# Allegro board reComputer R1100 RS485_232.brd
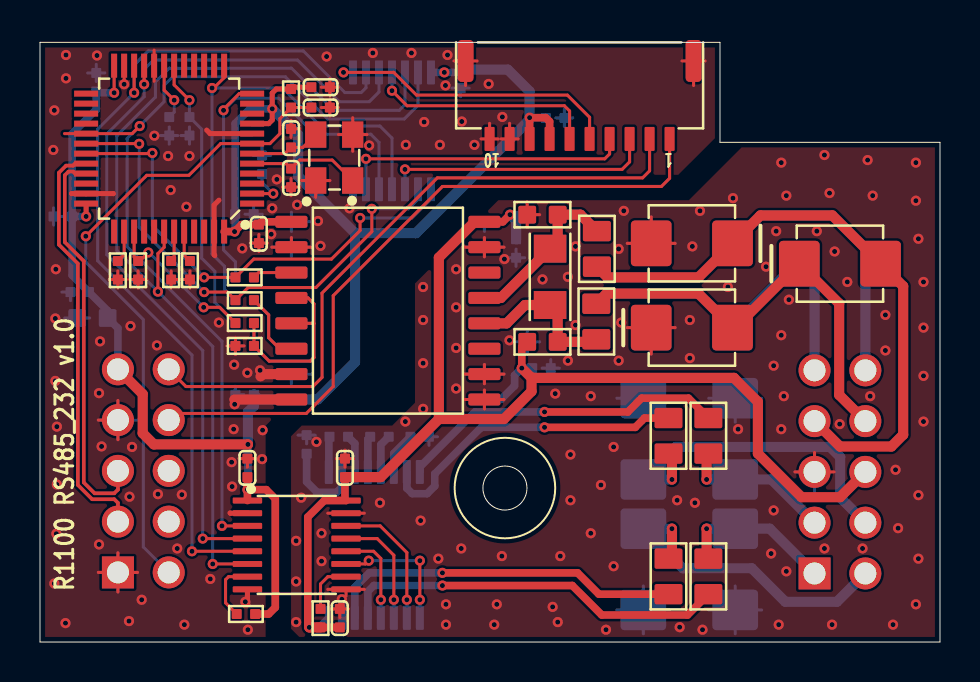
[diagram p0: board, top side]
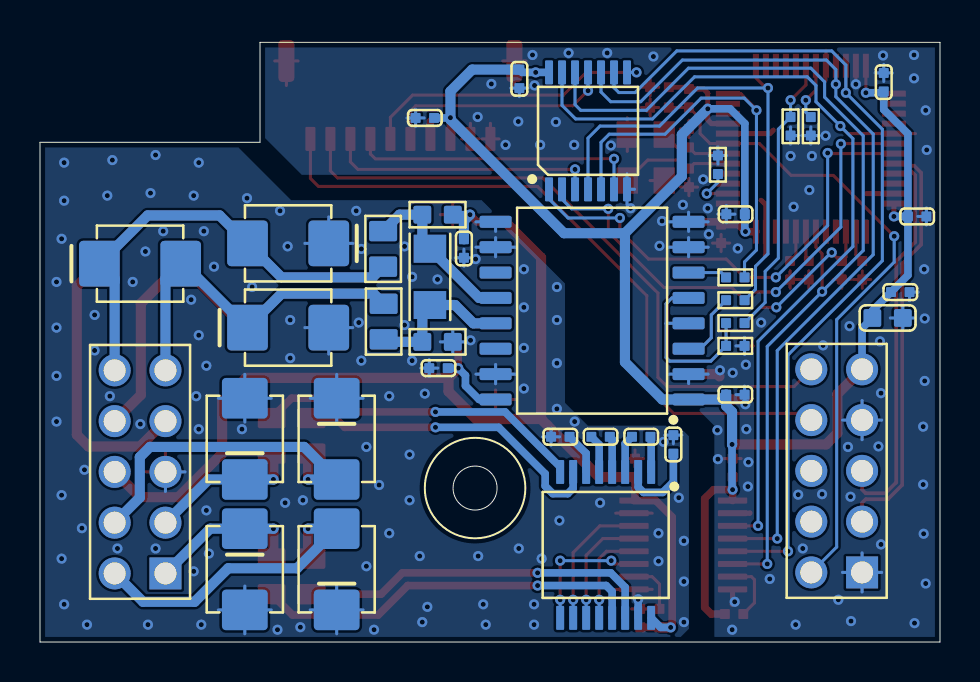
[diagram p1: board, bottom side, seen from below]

Outline 45 x 30 mm; copper layers: TOP, BOTTOM. Coordinates in mm from the lower left corner of the outline.
Outline path: circle c23.25,7.7 r1.1 ; 0,30 0,0 45,0 45,25 34,25 34,30 0,30

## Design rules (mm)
constraint set DEFAULT: min track width 0.152
net group DP1: nets USB_HUB1_DM2 USB_HUB1_DP2
net group N14652: nets N14652 N14700
net group N14712: nets N14712 N14756
net group RS485_2: nets EXT_RS485_1_B EXT_RS485_2_A
net group 5V_ISO_OUT: nets 5V_ISO_OUT RS485_1_A RS485_2_A
net group RS485_1: nets RS485_1_B

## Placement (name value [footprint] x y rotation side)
C1  100nF  [C0402]  10.94 20.42 270 top
C2  100nF  [C0402]  23.8 19.69 270 bottom
C3  100nF  [C0402]  10.22 21.4 0 bottom
C4  10uF  [C0603]  2.62 16.21 0 bottom
C5  1uF  [C0402]  14.03 27.76 180 top
C6  100nF  [C0402]  1.99 17.51 180 bottom
C7  100nF  [C0402]  10.23 12.38 180 bottom
C8  100nF  [C0402]  25.07 13.7 0 bottom
C9  100nF  [C0402]  14.03 26.74 0 top
C10  100nF  [C0402]  16.97 10.27 0 bottom
C11  100nF  [C0402]  14.94 10.27 0 bottom
C12  100nF  [C0402]  18.98 10.27 0 bottom
C13  100nF  [C0402]  13.33 9.89 90 bottom
C14  100nF  [C0402]  14.99 1.19 90 top
C15  100nF  [C0402]  2.81 28.01 90 bottom
C16  100nF  [C0402]  1.14 21.29 180 bottom
C17  100nF  [C0402]  15.25 8.71 90 top
C18  100nF  [C0402]  10.37 8.71 270 top
C19  100nF  [C0402]  21.03 28.17 270 bottom
C20  100nF  [C0402]  25.76 26.22 0 bottom
C21  22pF  [C0402]  12.55 23.22 270 top
C22  22pF  [C0402]  12.55 25.21 90 top
D1  SMBJ13CATR7  [DO_214AA_SMB]  32.59 15.73 180 top
D2  SMBJ13CATR7  [DO_214AA_SMB]  40 18.93 180 top
D3  SMBJ13CATR7  [DO_214AA_SMB]  32.59 19.95 0 top
D4  SMBJ13CATR7  [DO_214AA_SMB]  32.59 19.94 180 bottom
D5  SMBJ13CATR7  [DO_214AA_SMB]  40 18.93 0 bottom
D6  SMBJ13CATR7  [DO_214AA_SMB]  32.59 15.73 0 bottom
D7  SMBJ16CA  [DO_214AA_SMB]  30.17 3.64 270 bottom
D9  SMBJ16CA  [DO_214AA_SMB]  34.76 3.64 90 bottom
D10  SMBJ16CA  [DO_214AA_SMB]  30.17 10.16 90 bottom
D11  SMBJ16CA  [DO_214AA_SMB]  34.76 10.16 270 bottom
J1  Header 2x5 2.54  [HEADER2X5P_2D54_1_DIP]  5.17 8.56 0 bottom
J2  Header 2x5 2.54  [HEADER2X5P_2D54_1_DIP]  40 8.51 0 bottom
J3  1.0-10A-WT  [JST10_2P_1D0_12_35X4_3X3_2MM]  26.98 25.17 180 top
R1  10K  [R0603]  25.12 15.02 0 top
R2  33R  [R0402]  10.24 18.24 0 top
R3  RC0805FR-0710RL  [R0805]  27.82 16.03 90 top
R4  0R  [R0402]  10.24 15.96 0 top
R5  RC0805FR-0710RL  [R0805]  27.84 19.67 270 top
R6  33R  [R0402]  10.24 17.1 0 top
R7  10K  [R0402]  10.24 14.81 180 top
R8  120R  [R1206]  25.5 18.27 90 top
R9  10K  [R0402]  7.5 18.6 90 top
R10  10K  [R0603]  25.12 21.38 180 top
R11  10K  [R0402]  12.55 27.2 270 top
R12  10K  [R0603]  25.12 21.38 0 bottom
R13  33R  [R0402]  10.24 17.1 0 bottom
R14  RC0805FR-0710RL  [R0805]  27.84 19.67 270 bottom
R15  0R  [R0402]  10.24 15.96 0 bottom
R16  RC0805FR-0710RL  [R0805]  27.82 16.03 90 bottom
R17  33R  [R0402]  10.24 18.24 0 bottom
R18  10K  [R0402]  10.24 14.81 180 bottom
R19  120R  [R1206]  25.5 18.27 270 bottom
R20  10K  [R0603]  25.12 15.02 180 bottom
R25  10K  [R0402]  10.3 1.4 180 top
R26  10K  [R0402]  14.03 1.19 90 top
R27  10K  [R0402]  4.91 18.6 270 top
R28  10K  [R0402]  11.1 23.88 270 bottom
R29  10K  [R0402]  3.89 18.6 270 top
R30  10K  [R0402]  7.47 25.8 270 bottom
R31  10K  [R0402]  6.46 25.8 90 bottom
R32  10K  [R0402]  6.56 18.6 90 top
R33  100R  [R0805]  31.42 3.28 90 top
R34  100R  [R0805]  33.42 3.28 90 top
R35  100R  [R0805]  31.42 10.32 270 top
R36  100R  [R0805]  33.42 10.32 270 top
U1  CA-IS3082WX  [SOIC16_1R27_10R3X7R5MM]  17.4 16.58 270 top
U2  CH344L  [LQFP48-0_5-7X7X1_6MM]  6.46 24.68 180 top
U3  CA-IS3082WX  [SOIC16_1R27_10R3X7R5MM]  17.4 16.58 90 bottom
U4  SP3232EEA-L/TR  [SSOP16_0D65_6_3X5_3X2MM]  16.72 4.86 0 bottom
U25  74HC86T14-13  [TSSOP14_0D65_5X4D4X1D2MM]  17.6 25.57 180 bottom
U26  CA-IS3742HB  [SSOP16_0D635_4_9X3_9X1_75MM]  12.84 4.86 270 top
X1  8MHz  [X4-SMD-3_2X2_5X1_0MM]  14.71 24.24 90 top

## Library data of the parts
C1-C3 C5-C20 = CC: signal model: DEFAULT_CAPACITOR_100000pF_1_2
C4 C21 C22 = CC
D1-D7 D9-D11 = DIODE TVS BI-DIR
J1 J2 = Header 2X5
J3 = JST_10+2P
R1 R10 R12 R20 = R: signal model: DEFAULT_RESISTOR_10000OHM_1_2
R2-R9 R11 R13-R19 R25-R36 = R
U1 U3 = ISO3082DW
U2 = CH344L
U4 = SP3232EEA
U25 = SN74AHC86
U26 = CA-IS3742LB
X1 = XTAL_4P

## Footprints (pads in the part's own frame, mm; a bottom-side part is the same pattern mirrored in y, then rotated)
C0402
  rrect 0.5x0.5 smd: 1(-0.463,0) 2(0.463,0)
C0603
  rrect 0.889x0.889 smd: 1(-0.762,0) 2(0.762,0)
DO_214AA_SMB
  rrect 2.032x2.286 smd: 1(-2.032,0) 2(2.032,0)
HEADER2X5P_2D54_1_DIP
  rect 1.6x1.6 hole 1.1: 1(-1.27,5.08)
  round 1.6 hole 1.1: 2(1.27,5.08) 3(-1.27,2.54) 4(1.27,2.54) 5(-1.27,0) 6(1.27,0) 7(-1.27,-2.54) 8(1.27,-2.54) 9(-1.27,-5.08) 10(1.27,-5.08)
JST10_2P_1D0_12_35X4_3X3_2MM
  rrect 0.5x1.2 smd: 1(-4.5,0) 2(-3.5,0) 3(-2.5,0) 4(-1.5,0) 5(-0.5,0) 6(0.5,0) 7(1.5,0) 8(2.5,0) 9(3.5,0) 10(4.5,0)
  rrect 0.8x2.1 smd: S1(-5.7,-3.9) S2(5.7,-3.9)
LQFP48-0_5-7X7X1_6MM
  rect 1.2x0.3 smd: 1(-4.15,2.75) 2(-4.15,2.25) 3(-4.15,1.75) 4(-4.15,1.25) 5(-4.15,0.75) 6(-4.15,0.25) 7(-4.15,-0.25) 8(-4.15,-0.75) 9(-4.15,-1.25) 10(-4.15,-1.75) 11(-4.15,-2.25) 12(-4.15,-2.75) 25(4.15,-2.75) 26(4.15,-2.25) 27(4.15,-1.75) 28(4.15,-1.25) 29(4.15,-0.75) 30(4.15,-0.25) 31(4.15,0.25) 32(4.15,0.75) 33(4.15,1.25) 34(4.15,1.75) 35(4.15,2.25) 36(4.15,2.75)
  rect 0.3x1.2 smd: 13(-2.75,-4.15) 14(-2.25,-4.15) 15(-1.75,-4.15) 16(-1.25,-4.15) 17(-0.75,-4.15) 18(-0.25,-4.15) 19(0.25,-4.15) 20(0.75,-4.15) 21(1.25,-4.15) 22(1.75,-4.15) 23(2.25,-4.15) 24(2.75,-4.15) 37(2.75,4.15) 38(2.25,4.15) 39(1.75,4.15) 40(1.25,4.15) 41(0.75,4.15) 42(0.25,4.15) 43(-0.25,4.15) 44(-0.75,4.15) 45(-1.25,4.15) 46(-1.75,4.15) 47(-2.25,4.15) 48(-2.75,4.15)
R0402
  rrect 0.5x0.5 smd: 1(-0.463,0) 2(0.463,0)
R0603
  rrect 0.889x0.889 smd: 1(-0.762,0) 2(0.762,0)
R0805
  rrect 1.016x1.397 smd: 1(-0.889,0) 2(0.889,0)
R1206
  rect 1.397x1.626 smd: 1(-1.41,0) 2(1.41,0)
SOIC16_1R27_10R3X7R5MM
  rrect 0.6x1.6 smd: 1(-4.445,-4.825) 2(-3.175,-4.825) 3(-1.905,-4.825) 4(-0.635,-4.825) 5(0.635,-4.825) 6(1.905,-4.825) 7(3.175,-4.825) 8(4.445,-4.825) 9(4.445,4.825) 10(3.175,4.825) 11(1.905,4.825) 12(0.635,4.825) 13(-0.635,4.825) 14(-1.905,4.825) 15(-3.175,4.825) 16(-4.445,4.825)
SSOP16_0D65_6_3X5_3X2MM
  rrect 0.4x1.2 smd: 1(-2.275,-3.65) 2(-1.625,-3.65) 3(-0.975,-3.65) 4(-0.325,-3.65) 5(0.325,-3.65) 6(0.975,-3.65) 7(1.625,-3.65) 8(2.275,-3.65) 9(2.275,3.65) 10(1.625,3.65) 11(0.975,3.65) 12(0.325,3.65) 13(-0.325,3.65) 14(-0.975,3.65) 15(-1.625,3.65) 16(-2.275,3.65)
SSOP16_0D635_4_9X3_9X1_75MM
  rrect 0.3x1.47 smd: 1(-2.223,-2.465) 2(-1.587,-2.465) 3(-0.953,-2.465) 4(-0.318,-2.465) 5(0.318,-2.465) 6(0.953,-2.465) 7(1.587,-2.465) 8(2.223,-2.465) 9(2.223,2.465) 10(1.587,2.465) 11(0.953,2.465) 12(0.318,2.465) 13(-0.318,2.465) 14(-0.953,2.465) 15(-1.587,2.465) 16(-2.223,2.465)
TSSOP14_0D65_5X4D4X1D2MM
  rrect 0.4x1.2 smd: 1(-1.95,-2.925) 2(-1.3,-2.925) 3(-0.65,-2.925) 4(0,-2.925) 5(0.65,-2.925) 6(1.3,-2.925) 7(1.95,-2.925) 8(1.95,2.925) 9(1.3,2.925) 10(0.65,2.925) 11(0,2.925) 12(-0.65,2.925) 13(-1.3,2.925) 14(-1.95,2.925)
X4-SMD-3_2X2_5X1_0MM
  rect 1.321x1.067 smd: 1(-1.15,-0.925) 2(1.15,-0.925) 3(1.15,0.925) 4(-1.15,0.925)

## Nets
3V3_RS485: C1.1 C3.1 C4.2 C5.2 C6.1 C7.1 C15.1 C16.1 C18.2 C19.1 C20.1 J1.9 J3.7 J3.8 R11.1 R25.1 U1.1 U2.9 U2.24 U2.36 U2.48 U3.1 U25.14(VCC) U26.1
5V_ISO_OUT: C2.1 C8.1 C14.1 C17.1 J2.6 R1.1 R12.1 R26.1 U1.16 U3.16 U4.16(VCC) U26.16
GND: C1.2 C3.2 C4.1 C5.1 C6.2 C7.2 C9.2 C15.2 C16.2 C18.1 C19.2 C20.2 C21.2 C22.2 J1.1 J1.7 J3.9 J3.10 J3.S1 J3.S2 R7.2 R9.1 R18.2 R27.2 R28.1 R29.2 R30.2 R31.1 R32.1 U1.2 U1.7 U1.8 U2.8 U2.20 U2.23 U2.35 U2.47 U3.2 U3.7 U3.8 U25.7 U26.2 U26.8 X1.2 X1.4
GND_ISO: C2.2 C8.2 C12.2 C13.2 C14.2 C17.2 D1.2 D3.1 D4.2 D6.1 D7.2 D9.1 D10.2 D11.1 J2.5 R10.2 R20.2 U1.9 U1.10 U1.15 U3.9 U3.10 U3.15 U4.15 U26.9 U26.15
CH344_RST: C9.1 J1.2 R11.2 U2.7
CH_RXD2: U2.22 U25.9 U26.5
CH_RXD3: U2.42 U25.12 U26.6(VO4)
CH_TXD2: U2.21 U25.10 U26.4
CH_TXD3: U2.29 U25.13 U26.3
CM4_OUT1_LED: J1.8 J3.1
CM4_OUT2_LED: J1.10 J3.2
EXT_RS232_1_RX: D9.2 J2.1 R34.2
EXT_RS232_1_TX: D7.1 J2.2 R33.2
EXT_RS232_2_RX: D11.2 J2.3 R36.2
EXT_RS232_2_TX: D10.1 J2.4 R35.2
EXT_RS485_1_A: D1.1 D2.2 J2.8 R3.2
EXT_RS485_1_B: D2.1 D3.2 J2.7 R5.2
EXT_RS485_2_A: D4.1 D5.2 J2.10 R14.2
EXT_RS485_2_B: D5.1 D6.2 J2.9 R16.2
RS232_LED1: J3.5 U25.8
RS232_LED2: J3.6 U25.11
RS232_RXD1: U4.12 U26.12
RS232_RXD2: U4.9 U26.11
RS232_TXD1: U4.11 U26.13
RS232_TXD2: U4.10 U26.14
RS485_1_A: R1.2 R3.1 R8.1 U1.12
RS485_1_B: R5.1 R8.2 R10.1 U1.13
RS485_2_A: R12.2 R14.1 R19.1 U3.12
RS485_2_B: R16.1 R19.2 R20.1 U3.13
RS485_DTR1: R4.1 R27.1 U2.39
RS485_DTR2: R15.1 R30.1 U2.18
RS485_LED1: J3.3 U25.3
RS485_LED2: J3.4 U25.6
RS485_RXD1: R2.1 U2.31 U25.1
RS485_RXD2: R13.1 U2.13 U25.4
RS485_TXD1: R6.1 U2.30 U25.2
RS485_TXD2: R17.1 U2.12 U25.5
USB_HUB1_DM2: J1.3 U2.32
USB_HUB1_DP2: J1.5 U2.33
XI: C21.1 U2.5 X1.1
XO: C22.1 U2.6(XO) X1.3
N02289: R2.2 U1.3
N02317: R4.2 R7.1 U1.4(\\R\E) U1.5
N02517: R6.2 U1.6
N03671: R13.2 U3.3
N03703: R15.2 R18.1 U3.4(\\R\E) U3.5
N03887: R17.2 U3.6
N14484: R33.1 U4.14
N14512: R35.1 U4.7
N14652: C10.1 U4.4
N14700: C10.2 U4.5
N14704: C13.1 U4.2
N14712: C11.1 U4.1
N14720: C12.1 U4.6
N14756: C11.2 U4.3
N15316: R31.2 U2.19
N19896: R9.2 U2.44
N22670: R25.2 U26.7
N23580: R26.2 U26.10
N26778: R29.1 U2.38
N27410: R28.2 U2.2
N30228: R32.2 U2.43
N33687: R34.1 U4.13
N34139: R36.1 U4.8

Pads without a net: J1 4 6; U1 11 14; U2 1 3 4 10 11 14 15 16 17 25 26 27 28 34 37 40 41 45 46; U3 11 14

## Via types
v1: diameter 0.508, hole 0.254, TOP to BOTTOM, 218 vias

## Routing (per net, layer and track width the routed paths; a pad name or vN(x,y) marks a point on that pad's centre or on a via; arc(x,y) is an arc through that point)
3V3_RS485: length 100.1
  TOP w0.152: U2.24 v1(3.71,27.48)
  TOP w0.254: U2.9 11.43,25.93 11.61,26.12 v1(11.61,26.68) 11.61,27.46 11.82,27.67 R11.1 12.64,27.76 C5.2 ; U2.36 v1(2.31,21.29)
  TOP w0.381: v1(10.37,7.62) 11.31,7.62 11.76,7.17 11.76,1.73 11.43,1.4 R25.1 ; v1(10.37,7.62) U26.1 ; v1(10.37,7.62) C18.2 ; J3.7 25.48,26.04 25.29,26.23 v1(24.48,26.23) J3.8 ; U2.48 v1(9.73,20.53) 10.08,20.88 C1.1 11.08,21.02 U1.1
  TOP w0.508: J1.9 5.14,12.4 5.14,10.45 5.69,9.89 v1(10.4,9.89)
  BOTTOM w0.381: v1(3.71,27.48) 2.88,27.48 C15.1 2.81,26.64 1.6,25.43 C16.1 ; C16.1 v1(2.31,21.29) ; C16.1 1.6,18.35 C6.1 3.38,16.57 C4.2 3.9,15.7 J1.9 ; v1(11.61,26.68) 10.49,26.68 9.76,25.94 C3.1 9.76,20.56 v1(9.73,20.53) ; v1(10.37,7.62) 10.4,7.65 v1(10.4,9.89) ; v1(24.48,26.23) 24.49,26.22 C20.1 ; U25.14 v1(20.22,28.5) 20.89,28.5 C19.1
  BOTTOM w0.508: v1(11.61,26.68) 12.91,25.38 12.91,23.3 15.75,20.45 ; 15.75,20.45 18.8,20.45 24.48,26.13 v1(24.48,26.23) 24.48,27.55 23.39,28.64 C19.1 ; 15.75,20.45 15.75,14 13.88,12.13 U3.1 10.94,12.13 C7.1 10.69,11.81 10.4,11.51 v1(10.4,9.89)
5V_ISO_OUT: length 64.9
  TOP w0.381: C14.1 R26.1 ; v1(24.09,13.7) 24.09,14.75 R1.1 ; C17.1 15.25,7.13 U26.16 14.22,7.08 13.39,6.25 13.39,0.81 v1(13.47,0.73) ; v1(23.5,21.38) 23.14,21.02 U1.16
  TOP w0.508: J2.6 40,7.25 38.08,7.25 35.89,9.43 35.89,12.02 34.7,13.21 24.58,13.21 ; 24.58,13.21 24.58,12.54 23.19,11.16 19.94,11.16 ; 24.58,13.21 v1(24.09,13.7) ; 19.94,11.16 17.04,8.25 C17.1 ; 19.94,11.16 19.94,19.23 21.73,21.02 U1.16 ; R26.1 v1(13.47,0.73)
  BOTTOM w0.381: R12.1 v1(23.5,21.38) ; C8.1 v1(24.09,13.7) 23.73,13.34 23.73,12.82 23.04,12.13 U3.16 ; U4.16 13.97,0.73 v1(13.47,0.73)
  BOTTOM w0.508: v1(23.5,21.38) 23.8,21.08 C2.1
GND: length 92.1
  TOP w0.152: 2.92,3.48 J1.1 ; J1.1 4.87,3.48 ; J1.1 3.9,4.46 ; J1.1 3.9,2.5 ; R27.2 4.91,18.56 ; R27.2 4.48,18.14 ; R27.2 4.91,17.71 ; R27.2 5.34,18.14 ; 32.68,27.84 J3.S1 ; J3.S1 32.1,29.07 ; J3.S1 33.26,29.07 ; C21.2 12.98,22.76 ; C21.2 12.12,22.76 ; C21.2 12.55,23.19 ; C21.2 12.55,22.33 ; J3.S2 21.86,29.07 ; J3.S2 21.28,27.84 ; J3.S2 20.7,29.07 ; 14.92,25.39 X1.2 ; X1.2 15.64,26.23 ; X1.2 16.35,25.39 ; X1.2 15.64,24.55 ; X1.4 14.5,23.09 ; X1.4 13.79,22.25 ; X1.4 13.07,23.09 ; J3.9 23.48,25.95 ; J3.9 23.05,25.17 ; J3.9 23.91,25.17 ; 6.56,17.71 R32.1 ; R32.1 6.56,18.56 ; R32.1 6.99,18.14 ; R9.1 7.5,18.56 ; R9.1 7.07,18.14 ; R9.1 7.5,17.71 ; 10.94,19.53 C1.2 ; C1.2 10.51,19.96 ; C1.2 11.37,19.96 ; C1.2 10.94,20.39 ; 10.37,8.75 C18.1 ; C18.1 9.94,9.18 ; C18.1 10.8,9.18 ; U1.2 12.57,20.23 ; U1.2 11.59,19.75 ; U1.2 13.55,19.75 ; 3.46,18.14 R29.2 ; R29.2 4.32,18.14 ; R29.2 3.89,18.56 ; R29.2 3.89,17.71 ; 3.9,10.12 J1.7 ; J1.7 3.9,12.08 ; J1.7 2.92,11.1 ; R7.2 10.2,14.81 ; R7.2 9.77,15.24 ; R7.2 9.34,14.81 ; R7.2 9.77,14.39 ; C9.2 14.92,26.74 ; C9.2 14.49,27.17 ; C9.2 14.49,26.31 ; C9.2 14.06,26.74 ; 5.71,29.61 U2.20 5.71,28.06 ; 22.05,25.17 J3.10 ; J3.10 22.48,25.95 ; J3.10 22.91,25.17 ; 14.06,27.76 C5.1 ; C5.1 14.49,27.33 ; C5.1 14.92,27.76 ; C5.1 14.49,28.19 ; U2.23 v1(4.21,27.9) ; C22.2 12.55,26.1 ; C22.2 12.55,25.24 ; C22.2 12.98,25.67
  TOP w0.254: 10.39,1.89 10.37,1.91 U26.8 ; U2.8 8.51,25.43 8.34,25.61 ; 8.95,22.1 8.71,21.87 U2.47 8.71,19.37 8.74,19.34 ; U26.2 9.52,6.44 9.5,6.46 ; 1.58,22.43 U2.35 3.66,22.43
  TOP w0.508: 11.03,13.29 11.14,13.4 U1.7 ; U1.8 9.72,12.13
  BOTTOM w0.152: 9.77,11.95 C7.2 ; C7.2 9.77,12.8 ; C7.2 10.2,12.38 ; 11.59,21.02 U3.8 ; U3.8 12.57,21.5 ; U3.8 12.57,20.54 ; U3.8 13.55,21.02 ; C20.2 26.22,26.65 ; C20.2 26.22,25.79 ; C20.2 26.65,26.22 ; C20.2 25.79,26.22 ; 1.24,16.21 C4.1 ; C4.1 1.86,15.59 ; C4.1 2.48,16.21 ; C4.1 1.86,16.83 ; U1.2 13.55,19.75 ; U1.2 12.57,20.23 ; U1.2 12.57,19.27 ; U1.2 11.59,19.75 ; 10.68,20.98 C3.2 ; C3.2 10.25,21.4 ; C3.2 11.11,21.4 ; C3.2 10.68,21.83 ; J1.7 4.87,11.1 ; J1.7 3.9,10.12 ; J1.7 2.92,11.1 ; J1.7 3.9,12.08 ; R31.1 6.89,25.34 ; R31.1 6.46,24.91 ; R31.1 6.03,25.34 ; R31.1 6.46,25.77 ; R30.2 7.47,25.77 ; R30.2 7.47,24.91 ; R30.2 7.04,25.34 ; 20.6,27.71 C19.2 ; C19.2 21.03,27.28 ; C19.2 21.46,27.71 ; R28.1 11.1,24.77 ; R28.1 11.53,24.34 ; R28.1 11.1,23.91 ; R28.1 10.68,24.34 ; 9.77,14.39 R7.2 ; R7.2 10.2,14.81 ; R7.2 9.77,15.24 ; C16.2 0.68,21.72 ; C16.2 0.68,20.86 ; C16.2 1.11,21.29 ; 2.92,3.48 J1.1 ; J1.1 4.87,3.48 ; J1.1 3.9,4.46 ; J1.1 3.9,2.5 ; U25.7 15.65,23.43 ; U25.7 15.27,22.65 ; U25.7 15.65,21.87 ; U1.7 13.55,13.4 ; U1.7 12.57,12.92 ; U1.7 11.59,13.4 ; 1.52,17.08 C6.2 1.09,17.51 ; 2.38,28.47 C15.2 ; C15.2 2.81,28.9 ; C15.2 2.81,28.04 ; C15.2 3.24,28.47
  vias: v1(0.72,26.6) v1(0.66,24.62) v1(0.72,2.93) v1(0.79,18.65) v1(0.77,16.19) v1(0.77,13.06) v1(0.82,5.42) v1(0.84,10.78) v1(0.84,7.88) v1(1.3,29.37) v1(1.3,28.2) v1(1.27,0.95) v1(2.85,29.34) v1(3,15.04) v1(2.95,12.45) v1(2.95,4.88) v1(3.08,9.79) v1(4.53,15.8) v1(4.47,7.27) v1(4.45,1.05) v1(4.6,9.76) v1(5.08,2.11) v1(5.72,25.33) v1(5.85,14.84) v1(5.9,7.4) v1(6.41,24.31) v1(6.53,22.61) v1(6.86,4.68) v1(7.09,7.37) v1(7.22,0.87) v1(7.32,21.77) v1(7.47,24.31) v1(8.51,3.16) v1(8.95,15.98) v1(9.58,9) v1(9.61,7.78) v1(9.71,13.87) v1(9.73,11.89) v1(9.68,10.65) v1(10.11,19.69) v1(10.27,2.01) v1(10.37,13.47) v1(10.39,0.62) v1(11,13.6) v1(11.13,10.6) v1(11.1,9.15) v1(11.61,21.7) v1(11.56,20.4) v1(11.84,23.15) v1(12.86,21.88) v1(13.9,21.06) v1(14.03,19.82) v1(14.33,29.29) v1(15.47,21.7) v1(16.46,24.84) v1(16.64,29.47) v1(18.29,24.87) v1(18.57,29.47) v1(19.21,26.02) v1(19.99,24.87) v1(20.27,27.84) v1(20.38,29.37) v1(21.09,26.04) v1(21.72,24.87) v1(22.43,27.92) v1(23.12,26.27)
GND_ISO: length 75
  TOP w0.152: D1.2 31.76,15.73 ; D1.2 30.56,14.41 ; D1.2 29.37,15.73 ; U1.9 22.22,12.61 ; U1.9 23.2,12.13 ; U1.9 21.24,12.13 ; U1.9 22.22,11.65 ; U1.10 23.2,13.4 ; U1.10 22.22,13.88 ; U1.10 21.24,13.4 ; U1.10 22.22,12.92 ; D3.1 31.76,19.95 ; D3.1 30.56,21.27 ; D3.1 29.37,19.95 ; R10.2 24.98,21.38 ; R10.2 24.36,22 ; R10.2 24.36,20.76 ; U1.15 23.2,19.75 ; U1.15 21.24,19.75 ; U1.15 22.22,20.23 ; U1.15 22.22,19.27 ; J2.5 39.71,8.51 ; J2.5 37.75,8.51 ; J2.5 38.73,9.49 ; 15.3,2.31 U26.9 ; U26.9 14.39,2.63 ; U26.9 16.22,2.63 ; 16.22,6.44 U26.15 14.39,6.44 ; 14.99,1.23 C14.2 ; C14.2 14.99,2.09 ; C14.2 15.42,1.66 ; C14.2 14.56,1.66 ; 15.25,8.75 C17.2 ; C17.2 15.25,9.6 ; C17.2 14.82,9.18 ; C17.2 15.68,9.18
  BOTTOM w0.152: 22.22,12.92 U1.10 ; U1.10 23.2,13.4 ; U1.10 22.22,13.88 ; U1.10 21.24,13.4 ; C12.2 19.87,10.27 ; C12.2 19.02,10.27 ; C12.2 19.45,9.84 ; C12.2 19.45,10.7 ; 23.8,18.79 C2.2 ; C2.2 23.8,19.65 ; C2.2 24.23,19.22 ; C2.2 23.38,19.22 ; U1.15 23.2,19.75 ; U1.15 21.24,19.75 ; U1.15 22.22,19.27 ; U1.15 22.22,20.23 ; 38.73,7.53 J2.5 37.75,8.51 ; D7.2 30.17,2.8 ; D7.2 30.17,0.41 ; D7.2 31.49,1.61 ; D7.2 28.85,1.61 ; D4.2 30.56,21.27 ; D4.2 29.37,19.94 ; D4.2 31.76,19.94 ; 12.9,10.35 C13.2 ; C13.2 13.33,9.92 ; C13.2 13.76,10.35 ; 33.44,1.61 D9.1 ; D9.1 36.08,1.61 ; D9.1 34.76,0.41 ; D9.1 34.76,2.8 ; 30.17,11 D10.2 ; D10.2 30.17,13.39 ; D10.2 28.85,12.2 ; D10.2 31.49,12.2 ; 23.2,21.02 U3.9 22.22,20.54 ; 25.11,13.7 C8.2 ; C8.2 25.54,14.13 ; C8.2 25.97,13.7 ; C8.2 25.54,13.27 ; D11.1 34.76,13.39 ; D11.1 34.76,11 ; D11.1 36.08,12.2 ; D11.1 33.44,12.2 ; R20.2 24.98,15.02 ; R20.2 24.36,14.39 ; R20.2 23.74,15.02 ; R20.2 24.36,15.64 ; D1.2 31.76,15.73 ; D1.2 29.37,15.73 ; D1.2 30.56,14.41
  BOTTOM w0.381: U4.15 v1(15.09,2.14)
  vias: v1(12.81,5.06) v1(12.81,3.03) v1(12.81,1) v1(13.06,7.22) v1(13.82,10.01) v1(14.08,5.44) v1(14.08,4.04) v1(17,6.97) v1(18.27,11.03) v1(19.03,6.08) v1(19.16,17.76) v1(19.16,16.11) v1(19.16,13.95) v1(19.16,11.66) v1(19.92,4.17) v1(20.3,1.89) v1(20.3,0.87) v1(20.81,18.65) v1(20.81,16.74) v1(20.81,14.71) v1(20.81,12.68) v1(21.06,4.68) v1(22.71,0.87) v1(22.84,1.89) v1(23.09,4.3) v1(23.22,19.16) v1(23.47,15.09) v1(25.13,18.14) v1(25.63,1.76) v1(25.76,12.43) v1(25.89,1) v1(26.01,4.3) v1(26.4,18.27) v1(26.4,14.08) v1(26.52,9.38) v1(26.52,7.09) v1(26.78,19.79) v1(26.78,15.86) v1(27.54,12.3) v1(27.54,5.44) v1(28.05,7.85) v1(28.3,0.62) v1(28.68,9.76) v1(28.68,3.79) v1(28.94,19.67) v1(28.94,14.08) v1(29.06,15.98) v1(29.19,21.57) v1(31.86,7.09) v1(31.98,0.74) v1(32.49,16.11) v1(32.49,14.2) v1(32.62,19.79) v1(32.75,6.97) v1(33,21.57) v1(33.13,0.62) v1(34.4,17.76) v1(34.65,22.21) v1(34.9,10.65) v1(36.3,18.78) v1(36.56,4.43) v1(36.68,13.82) v1(36.68,6.58) v1(36.81,20.55) v1(36.94,0.87) v1(37.06,23.98) v1(37.06,15.35) v1(37.06,10.65) v1(37.19,12.3) v1(37.32,22.33) v1(37.32,3.54) v1(37.44,17.13) v1(38.84,20.55) v1(39.22,24.36) v1(39.22,4.68) v1(39.48,22.46) v1(39.6,0.87) v1(39.73,19.54) v1(39.98,10.9) v1(40.37,18.01) v1(41.13,4.68) v1(41.38,24.11) v1(41.51,12.3) v1(41.64,22.33) v1(42.27,16.36) v1(42.27,14.59) v1(42.65,0.87) v1(42.78,8.62) v1(42.91,5.7) v1(43.79,23.98) v1(43.79,22.08) v1(43.79,1.89) v1(43.92,20.17) v1(43.92,7.35) v1(43.92,4.17) v1(44.18,18.01) v1(44.18,15.73) v1(44.18,13.32) v1(44.18,11.03)
CH344_RST: length 32.9
  TOP w0.152: v1(2.29,20.3) 5.34,23.35 7.45,23.35 9.03,24.93 U2.7 11.5,24.93 11.99,25.43 11.99,26.18 R11.2 C9.1
  BOTTOM w0.152: J1.2 5.17,4.75 5.17,16.13 2.29,19.01 v1(2.29,20.3)
CH_RXD2: length 44.8
  TOP w0.152: U2.22 v1(4.71,27.48) ; U26.5 v1(7.6,4.54)
  BOTTOM w0.152: v1(7.6,4.54) 7.6,14.36 2.88,19.07 2.88,25.66 v1(4.71,27.48) 4.71,28.86 5.41,29.57 13.16,29.57 15.24,27.49 16.06,27.49 16.3,27.73 U25.9
CH_RXD3: length 47.1
  TOP w0.152: U26.6 v1(8.64,3.9) ; v1(5.9,17.53) 5.9,19.44 6.21,19.75 U2.42
  BOTTOM w0.152: U25.12 18.25,26.89 17.96,26.6 14.69,26.6 12.58,28.71 6.46,28.71 5.77,28.02 5.77,27.26 3.84,25.33 3.84,19.59 v1(5.9,17.53) 8.64,14.79 v1(8.64,3.9)
CH_TXD2: length 43.4
  TOP w0.152: U2.21 v1(5.21,27.9) ; U26.4 v1(8.14,5.17)
  BOTTOM w0.152: U25.10 16.95,27.52 16.46,27.03 14.97,27.03 12.88,29.11 5.68,29.11 5.21,28.64 v1(5.21,27.9) 5.21,27.28 3.34,25.41 3.34,19.38 8.14,14.58 v1(8.14,5.17)
CH_TXD3: length 45.6
  TOP w0.152: v1(4.98,25.81) 4.61,25.43 U2.29 1.23,25.43 ; U26.3 v1(9.1,5.81)
  BOTTOM w0.152: v1(9.1,5.81) 9.1,15.04 4.36,19.78 4.36,25.19 v1(4.98,25.81) 6.2,27.03 6.2,27.84 6.64,28.28 12.27,28.28 14.38,26.17 18.22,26.17 18.9,26.85 U25.13
CM4_OUT1_LED: length 34.7
  TOP w0.152: J3.1 31.48,23.2 31.07,22.79 20.12,22.79 14.66,17.33 14.66,12.78 13.31,11.44 6.77,11.44 J1.8
CM4_OUT2_LED: length 32.9
  TOP w0.152: J3.2 30.48,23.57 30.13,23.22 19.87,23.22 14.1,17.46 14.1,13.24 13.64,12.78 7.3,12.78 J1.10
EXT_RS232_1_RX: length 7.9
  TOP w0.508: R34.2 33.33,4.26 v1(33.33,5.67)
  BOTTOM w0.508: v1(33.33,5.67) D9.2 36.49,5.67 J2.1
EXT_RS232_1_TX: length 16.2
  TOP w0.508: v1(31.6,5.67) 31.6,4.34 R33.2
  BOTTOM w0.508: J2.2 39.85,2.01 37.27,2.01 35.59,3.69 32.15,3.69 D7.1 v1(31.6,5.67)
EXT_RS232_2_RX: length 7.6
  TOP w0.508: R36.2 33.33,9.34 v1(33.33,8.13)
  BOTTOM w0.508: J2.3 36.57,8.13 D11.2 v1(33.33,8.13)
EXT_RS232_2_TX: length 17.3
  TOP w0.508: R35.2 31.6,9.25 v1(31.6,8.13)
  BOTTOM w0.508: J2.4 40.01,7.23 40.01,9.25 39.5,9.76 31.8,9.76 D10.1 v1(31.6,8.13)
EXT_RS485_1_A: length 21.6
  TOP w0.508: J2.8 39.96,12.36 39.96,16.94 D2.2 34.76,15.73 D1.1 32.92,17.43 28.33,17.43 R3.2
EXT_RS485_1_B: length 30.9
  TOP w0.508: R5.2 28.38,18.24 32.92,18.24 D3.2 36.02,21.34 39.62,21.34 D2.1 43.16,17.8 43.16,10.37 42.57,9.78 40,9.78 J2.7
EXT_RS485_2_A: length 22.3
  BOTTOM w0.508: R14.2 28.38,18.24 32.92,18.24 D4.1 36.02,21.34 39.62,21.34 D5.2 41.27,18.17 J2.10
EXT_RS485_2_B: length 18
  BOTTOM w0.508: J2.9 38.73,18.17 D5.1 37.83,18.93 D6.2 32.92,17.43 28.33,17.43 R16.2
RS232_LED1: length 14.8
  TOP w0.152: J3.5 27.48,26.25 26.37,27.36 18.83,27.36 17.69,28.5 v1(15.18,28.5)
  BOTTOM w0.152: U25.8 v1(15.18,28.5)
RS232_LED2: length 11.6
  TOP w0.152: v1(17.6,27.58) 18.35,26.83 26.22,26.83 26.48,26.57 J3.6
  BOTTOM w0.152: U25.11 v1(17.6,27.58)
RS232_RXD1: length 4.9
  TOP w0.152: v1(17.04,2.11) 17.04,4.18 16.68,4.54 U26.12
  BOTTOM w0.152: U4.12 v1(17.04,2.11)
RS232_RXD2: length 6.6
  TOP w0.152: v1(16.44,4.07) 16.27,3.9 U26.11 ; v1(18.99,4.07) v1(18.99,2.11)
  BOTTOM w0.152: U4.9 v1(18.99,2.11) ; v1(16.44,4.07) v1(18.99,4.07)
RS232_TXD1: length 5.9
  TOP w0.152: v1(17.69,2.11) 17.69,4.34 16.86,5.17 U26.13
  BOTTOM w0.152: U4.11 v1(17.69,2.11)
RS232_TXD2: length 6.9
  TOP w0.152: v1(18.34,2.11) 18.34,4.48 17.01,5.81 U26.14
  BOTTOM w0.152: U4.10 v1(18.34,2.11)
RS485_1_A: length 7.6
  TOP w0.508: U1.12 23.33,15.94 24.25,16.86 R8.1 25.88,16.48 R1.2 27.69,15.02 R3.1
RS485_1_B: length 8.5
  TOP w0.508: R5.1 27.02,21.38 R10.1 25.88,20.06 R8.2 23.04,17.21 U1.13
RS485_2_A: length 8.5
  BOTTOM w0.508: U3.12 23.04,17.21 R19.1 25.88,20.06 R12.2 27.02,21.38 R14.1
RS485_2_B: length 7.6
  BOTTOM w0.508: U3.13 23.33,15.94 24.25,16.86 R19.2 25.88,16.48 R20.1 27.69,15.02 R16.1
RS485_DTR1: length 8.1
  TOP w0.152: v1(8.18,16.74) 8.99,16.74 R4.1 ; U2.39 4.71,19.26 R27.1 4.99,19.06 v1(5.41,19.49)
  BOTTOM w0.152: v1(8.18,16.74) 5.44,19.49 v1(5.41,19.49)
RS485_DTR2: length 14.1
  TOP w0.152: v1(7.47,27.11) 6.71,27.87 U2.18
  BOTTOM w0.152: v1(7.47,27.11) R30.1 8.08,25.65 8.08,19.2 8.74,18.54 8.74,16.99 R15.1
RS485_LED1: length 13.5
  TOP w0.152: v1(18.25,23.65) 29.11,23.65 29.48,24.02 J3.3
  BOTTOM w0.152: U25.3 v1(18.25,23.65)
RS485_LED2: length 14.6
  TOP w0.152: v1(16.3,24.17) 28.24,24.17 28.48,24.42 J3.4
  BOTTOM w0.152: U25.6 v1(16.3,24.17)
RS485_RXD1: length 24.4
  TOP w0.152: v1(8.21,18.24) R2.1 10.69,19.16 14.57,19.16 16.01,20.59 v1(16.01,21.22) ; U2.31 5.59,24.43 v1(5.62,24.47)
  BOTTOM w0.152: v1(16.01,21.22) 18.6,21.22 19.55,22.17 U25.1 ; v1(8.21,18.24) 5.62,20.83 v1(5.62,24.47)
RS485_RXD2: length 25.1
  TOP w0.152: U2.13 9.21,28.23 8.69,27.72 v1(8.6,27.72)
  BOTTOM w0.152: U25.4 17.6,25.21 17,25.81 14.03,25.81 12.12,27.72 v1(8.6,27.72) 8.6,19.42 9.22,18.8 9.22,17.65 R13.1
RS485_TXD1: length 25.5
  TOP w0.152: U2.30 4.95,24.93 v1(4.96,24.92) ; v1(8.21,17.51) 9.37,17.51 R6.1 10.41,17.74 13.8,17.74 16.59,20.53 v1(16.59,21.67)
  BOTTOM w0.152: v1(4.96,24.92) 4.96,20.76 v1(8.21,17.51) ; v1(16.59,21.67) 18.42,21.67 18.9,22.15 U25.2
RS485_TXD2: length 21.7
  TOP w0.152: U2.12 9.96,27.43 9.18,26.65 v1(9.18,26.6)
  BOTTOM w0.152: U25.5 16.95,25 16.54,25.41 13.75,25.41 11.94,27.21 9.79,27.21 v1(9.18,26.6) 9.18,19.61 9.77,19.02 R17.1
USB_HUB1_DM2: length 20.9
  TOP w0.183: J1.3 3.9,6.96 3.71,7.14 2.61,7.14 1.89,7.86 1.89,18.93 0.94,19.88 0.94,23.48 1.3,23.83 1.66,23.83 1.76,23.93 U2.32
USB_HUB1_DP2: length 19.9
  TOP w0.183: J1.5 3.9,7.62 3.71,7.44 2.73,7.44 2.19,7.98 2.19,19.06 1.24,20 1.24,23.35 1.42,23.54 1.66,23.54 1.76,23.43 U2.33
XI: length 5.7
  TOP w0.152: U2.5 12.3,23.93 C21.1 12.98,24.11 14.61,24.11 X1.1
XO: length 3.6
  TOP w0.152: X1.3 13.14,24.75 C22.1 12.24,24.43 U2.6
N02289: length 2
  TOP w0.152: R2.2 10.94,18.48 U1.3
N02317: length 9.6
  TOP w0.152: R4.2 R7.1 11.46,14.05 13.52,14.05 13.7,14.23 13.7,15.93 ; 13.7,15.93 13.7,16.92 13.4,17.21 U1.4 ; 13.7,15.93 13.68,15.94 U1.5
N02517: length 3.5
  TOP w0.152: U1.6 11.98,14.67 11.43,15.22 11.43,16.36 R6.2
N03671: length 3.5
  BOTTOM w0.152: U3.3 11.98,14.67 11.43,15.22 11.43,16.36 R13.2
N03703: length 9.6
  BOTTOM w0.152: 13.7,15.93 13.7,14.23 13.52,14.05 11.46,14.05 R18.1 R15.2 ; 13.7,15.93 13.7,16.92 13.4,17.21 U3.5 ; 13.7,15.93 13.68,15.94 U3.4
N03887: length 2
  BOTTOM w0.152: U3.6 10.94,18.48 R17.2
N14484: length 18
  TOP w0.381: v1(20.12,3.46) 26.88,3.46 27.94,2.39 R33.1
  BOTTOM w0.381: v1(20.12,3.46) 16.46,3.46 15.74,2.74 U4.14
N14512: length 15.9
  TOP w0.381: v1(25.23,10.74) 29.76,10.74 30.23,11.2 R35.1
  BOTTOM w0.381: U4.7 18.34,7.69 18.61,7.42 19.36,7.42 19.74,7.8 19.74,8.41 22.07,10.74 v1(25.23,10.74)
N14652: length 1.8
  BOTTOM w0.381: U4.4 16.39,10.15 C10.1
N14700: length 1.9
  BOTTOM w0.381: U4.5 17.04,9.88 C10.2
N14704: length 4.3
  BOTTOM w0.381: C13.1 13.33,8.01 13.86,7.48 14.82,7.48 15.09,7.75 U4.2
N14712: length 1.8
  BOTTOM w0.381: U4.1 14.44,10.23 C11.1
N14720: length 2.1
  BOTTOM w0.381: C12.1 17.69,9.44 U4.6
N14756: length 1.9
  BOTTOM w0.381: C11.2 15.74,9.93 U4.3
N15316: length 2.9
  TOP w0.152: v1(6.71,27.11) 6.21,27.61 U2.19
  BOTTOM w0.152: v1(6.71,27.11) 6.71,26.51 R31.2
N19896: length 1.6
  TOP w0.152: U2.44 7.21,19.35 R9.2
N22670: length 3.1
  TOP w0.152: R25.2 9.28,1.96 9.28,3.12 9.43,3.27 U26.7
N23580: length 2.7
  TOP w0.152: U26.10 14.39,3.27 14.03,2.9 R26.2
N26778: length 1.6
  TOP w0.152: R29.1 4.21,19.38 U2.38
N27410: length 2.3
  TOP w0.152: U2.2 v1(11.66,22.43)
  BOTTOM w0.152: R28.2 11.1,22.99 v1(11.66,22.43)
N30228: length 1.5
  TOP w0.152: R32.2 6.71,19.21 U2.43
N33687: length 19.5
  TOP w0.381: v1(20.12,2.83) 26.61,2.83 28.09,1.35 32.38,1.35 R34.1
  BOTTOM w0.381: U4.13 16.39,2.53 16.69,2.83 v1(20.12,2.83)
N34139: length 16.5
  TOP w0.381: R36.1 32.43,12.2 30.08,12.2 29.39,11.51 v1(25.23,11.51)
  BOTTOM w0.381: v1(25.23,11.51) 21.75,11.51 18.99,8.76 U4.8

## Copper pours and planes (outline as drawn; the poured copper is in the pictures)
GND on TOP: 0.25,29.75 33.75,29.75 33.75,25.21 31.91,23.37 22.33,23.37 16.82,17.86 16.82,13.14 15.3,11.61 12.78,11.61 12.04,10.88 12.04,0.54 11.76,0.25 0.25,0.25 ; 8 cut-outs
GND on BOTTOM: 0.25,29.75 33.75,29.75 33.75,25.21 31.91,23.37 22.33,23.37 16.82,17.86 16.82,13.14 15.3,11.61 12.78,11.61 12.04,10.88 12.04,0.54 11.76,0.25 0.25,0.25 ; 15 cut-outs
GND_ISO on TOP: 35.08,24.75 44.75,24.75 44.75,0.25 12.96,0.25 12.55,0.67 12.55,10.29 13.09,10.83 17.61,10.83 18.75,11.97 18.75,17.94 22.92,22.1 32.44,22.1 ; 4 cut-outs
GND_ISO on BOTTOM: 35.08,24.75 44.75,24.75 44.75,0.25 12.96,0.25 12.55,0.67 12.55,10.29 13.09,10.83 17.61,10.83 18.75,11.97 18.75,17.94 22.92,22.1 32.44,22.1 ; 1 cut-out

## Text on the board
Ref Des/Silkscreen Top: R1100 RS485_232 v1.0
PAGE_OUTLINE: HALF+PLATING | LAYER 1 - PRIMARY SIDE - SIGNAL | LAYER 2 - SECONDARY SIDE - SIGNAL | 50ohm SINGLE ENDED | IMPEDANCE CONTROL | +/- 10% | Clearance from Cu 5mil | 7.19/4.5 | COPPER WEIGHT | (OZ) | 1oz | TRACE WIDTH | (mil) | 90ohm DIFFERENTIAL | TRACE WIDTH/SPACE | 100ohm DIFFERENTIAL | 2 LAYER#---1.6MM | LAYER# | LAYER STACK-UP - ALL DIMENSIONS IN INCHES
User.23: FIGURE | FINISHED_SIZE | 10.0 | 43.31 | DRILL CHART: TOP to BOTTOM | ALL UNITS ARE IN MILS | PLATED | QTY | 218 | 20 | 238 | TOTAL HOLES:
